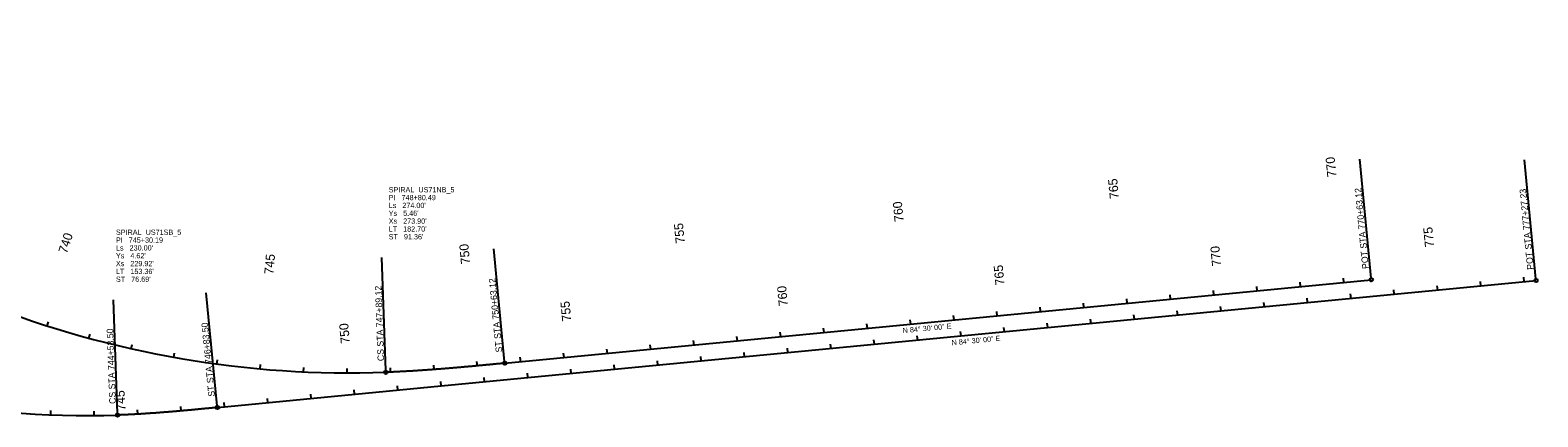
# Model space of a CAD drawing. Extents: x 2819977 to 2827606, y 113942 to 150283.
# Drawn here: x 2824142 to 2827606, y 145321 to 146209 of the extents above; entities that cross this region are included whole.
import ezdxf

# ---------------------------------------------------------------- set-up
doc = ezdxf.new("R2010")
doc.units = 0
for name, color, linetype in [('Level 63', 7, 'Continuous'), ('Roadway-Safety', 7, 'Continuous'), ('Roadway-Walls', 7, 'Continuous'), ('Utility-Power', 7, 'Continuous')]:
    doc.layers.add(name, color=color, linetype=linetype)

msp = doc.modelspace()

# ---------------------------------------------------------------- linework, layer by layer
at = {"layer": 'Level 63'}
for centre in [(2827223.3, 145635.6), (2827601.9, 145633.9), (2825232.5, 145443.9), (2824959.3, 145423.1), (2824572.2, 145342.1), (2824342.9, 145324.7)]:
    msp.add_circle(centre, 4, dxfattribs=at)
at = {"layer": 'Roadway-Safety'}
for p, q in [((2827222.9, 145639.6), (2827196.6, 145913)), ((2827601.6, 145637.8), (2827575.2, 145911.3)), ((2825232.1, 145447.9), (2825207.2, 145706.4)), ((2824959.2, 145427.1), (2824949.8, 145686.6)), ((2824342.8, 145328.7), (2824333.4, 145589.5)), ((2824571.8, 145346.1), (2824546.8, 145605.9))]:
    msp.add_line(p, q, dxfattribs=at)
at = {"layer": 'Utility-Power'}
for p, q in [((2825086.6, 145391.7), (2827601.9, 145633.9)), ((2825232.5, 145443.9), (2827223.3, 145635.6)), ((2826961.4, 145610.3), (2826960.4, 145620.3)), ((2827060.9, 145619.9), (2827060, 145629.9)), ((2827160.5, 145629.5), (2827159.5, 145639.5)), ((2827375.8, 145612.1), (2827374.8, 145622)), ((2827475.3, 145621.7), (2827474.3, 145631.6)), ((2827574.8, 145631.2), (2827573.9, 145641.2)), ((2826662.8, 145581.6), (2826661.8, 145591.5)), ((2826762.3, 145591.2), (2826761.3, 145601.1)), ((2826861.8, 145600.8), (2826860.9, 145610.7)), ((2826977.6, 145573.7), (2826976.6, 145583.7)), ((2827077.1, 145583.3), (2827076.2, 145593.3)), ((2827176.7, 145592.9), (2827175.7, 145602.9)), ((2827276.2, 145602.5), (2827275.3, 145612.4)), ((2826264.6, 145543.3), (2826263.6, 145553.2)), ((2826364.1, 145552.8), (2826363.2, 145562.8)), ((2826463.7, 145562.4), (2826462.7, 145572.4)), ((2826563.2, 145572), (2826562.3, 145582)), ((2826679, 145545), (2826678, 145554.9)), ((2826778.5, 145554.6), (2826777.6, 145564.5)), ((2826878.1, 145564.1), (2826877.1, 145574.1)), ((2824181.4, 145529.5), (2824184.4, 145539)), ((2825866.4, 145504.9), (2825865.5, 145514.9)), ((2825966, 145514.5), (2825965, 145524.5)), ((2826065.5, 145524.1), (2826064.6, 145534)), ((2826165.1, 145533.7), (2826164.1, 145543.6)), ((2826280.8, 145506.6), (2826279.9, 145516.6)), ((2826380.4, 145516.2), (2826379.4, 145526.2)), ((2826479.9, 145525.8), (2826478.9, 145535.8)), ((2826579.4, 145535.4), (2826578.5, 145545.4)), ((2824277.3, 145501.2), (2824279.9, 145510.9)), ((2824374.3, 145477.2), (2824376.5, 145487)), ((2825567.8, 145476.2), (2825566.9, 145486.1)), ((2825667.4, 145485.7), (2825666.4, 145495.7)), ((2825766.9, 145495.3), (2825765.9, 145505.3)), ((2825982.2, 145477.9), (2825981.2, 145487.8)), ((2826081.7, 145487.5), (2826080.8, 145497.4)), ((2826181.3, 145497.1), (2826180.3, 145507)), ((2824472.4, 145457.4), (2824474.1, 145467.3)), ((2824571.1, 145442), (2824572.5, 145451.9)), ((2825169.7, 145437.9), (2825168.7, 145447.9)), ((2825269.2, 145447.4), (2825268.2, 145457.4)), ((2825368.7, 145457), (2825367.8, 145466.9)), ((2825468.3, 145466.6), (2825467.3, 145476.5)), ((2825584, 145439.6), (2825583.1, 145449.5)), ((2825683.6, 145449.1), (2825682.6, 145459.1)), ((2825783.1, 145458.7), (2825782.2, 145468.7)), ((2825882.7, 145468.3), (2825881.7, 145478.3)), ((2824670.5, 145430.8), (2824671.4, 145440.8)), ((2824770.3, 145424), (2824770.7, 145434)), ((2824870.2, 145421.6), (2824870.3, 145431.6)), ((2824959.3, 145423.1), (2824959.3, 145423.1)), ((2824970.2, 145423.5), (2824969.8, 145433.5)), ((2825070, 145429.4), (2825069.3, 145439.4)), ((2825185.9, 145401.2), (2825184.9, 145411.2)), ((2825285.4, 145410.8), (2825284.5, 145420.8)), ((2825385, 145420.4), (2825384, 145430.3)), ((2825484.5, 145430), (2825483.5, 145439.9)), ((2824572.2, 145342.1), (2825086.6, 145391.7)), ((2824887.3, 145372.5), (2824886.3, 145382.4)), ((2824986.8, 145382), (2824985.8, 145392)), ((2825086.3, 145391.6), (2825085.4, 145401.6)), ((2824489.1, 145334.3), (2824488.2, 145344.3)), ((2824588.6, 145343.7), (2824587.7, 145353.7)), ((2824688.2, 145353.3), (2824687.2, 145363.2)), ((2824787.7, 145362.9), (2824786.8, 145372.8)), ((2824189.5, 145325.4), (2824189.9, 145335.3)), ((2824289.4, 145323.5), (2824289.4, 145333.5)), ((2824342.9, 145324.7), (2824342.9, 145324.7)), ((2824389.4, 145326.9), (2824388.8, 145336.9))]:
    msp.add_line(p, q, dxfattribs=at)
for centre, radius, start, end in [((2824274.6, 147233.3), 1909.9, 212.4335, 272.05), ((2824876.4, 147713.4), 2291.8, 224.9911, 272.075)]:
    msp.add_arc(centre, radius, start, end, dxfattribs=at)
for points in [[(2825232.5, 145443.9), (2825228.8, 145443.5), (2825225.1, 145443.2), (2825221.4, 145442.8), (2825217.8, 145442.5), (2825214.1, 145442.1), (2825210.4, 145441.8), (2825206.7, 145441.4), (2825203, 145441), (2825199.3, 145440.7), (2825195.6, 145440.3), (2825192, 145440), (2825188.3, 145439.6), (2825184.6, 145439.3), (2825180.9, 145438.9), (2825177.2, 145438.6), (2825173.5, 145438.3), (2825169.8, 145437.9), (2825166.2, 145437.6), (2825162.5, 145437.2), (2825158.8, 145436.9), (2825155.1, 145436.5), (2825151.4, 145436.2), (2825147.7, 145435.9), (2825144, 145435.5), (2825140.3, 145435.2), (2825136.7, 145434.9), (2825133, 145434.6), (2825129.3, 145434.2), (2825125.6, 145433.9), (2825121.9, 145433.6), (2825118.2, 145433.3), (2825114.5, 145433), (2825110.8, 145432.6), (2825107.1, 145432.3), (2825103.5, 145432), (2825099.8, 145431.7), (2825096.1, 145431.4), (2825092.4, 145431.1), (2825088.7, 145430.8), (2825085, 145430.5), (2825081.3, 145430.3), (2825077.6, 145430), (2825073.9, 145429.7), (2825070.2, 145429.4), (2825066.5, 145429.1), (2825062.8, 145428.9), (2825059.2, 145428.6), (2825055.5, 145428.3), (2825051.8, 145428.1), (2825048.1, 145427.8), (2825044.4, 145427.6), (2825040.7, 145427.3), (2825037, 145427.1), (2825033.3, 145426.8), (2825029.6, 145426.6), (2825025.9, 145426.4), (2825022.2, 145426.1), (2825018.5, 145425.9), (2825014.8, 145425.7), (2825011.1, 145425.5), (2825007.4, 145425.3), (2825003.7, 145425.1), (2825000, 145424.9), (2824996.3, 145424.7), (2824992.6, 145424.5), (2824988.9, 145424.3), (2824985.2, 145424.1), (2824981.5, 145424), (2824977.8, 145423.8), (2824974.1, 145423.6), (2824970.4, 145423.5), (2824966.7, 145423.3), (2824963, 145423.2), (2824959.3, 145423.1)], [(2824572.2, 145342.1), (2824569.1, 145341.8), (2824566, 145341.5), (2824562.9, 145341.2), (2824559.8, 145340.9), (2824556.7, 145340.6), (2824553.7, 145340.3), (2824550.6, 145340), (2824547.5, 145339.7), (2824544.4, 145339.5), (2824541.3, 145339.2), (2824538.2, 145338.9), (2824535.1, 145338.6), (2824532, 145338.3), (2824528.9, 145338), (2824525.8, 145337.7), (2824522.7, 145337.4), (2824519.6, 145337.1), (2824516.5, 145336.8), (2824513.4, 145336.5), (2824510.3, 145336.3), (2824507.2, 145336), (2824504.1, 145335.7), (2824501, 145335.4), (2824498, 145335.1), (2824494.9, 145334.9), (2824491.8, 145334.6), (2824488.7, 145334.3), (2824485.6, 145334), (2824482.5, 145333.8), (2824479.4, 145333.5), (2824476.3, 145333.2), (2824473.2, 145333), (2824470.1, 145332.7), (2824467, 145332.4), (2824463.9, 145332.2), (2824460.8, 145331.9), (2824457.7, 145331.7), (2824454.6, 145331.4), (2824451.5, 145331.2), (2824448.4, 145330.9), (2824445.3, 145330.7), (2824442.2, 145330.5), (2824439.1, 145330.2), (2824436, 145330), (2824432.9, 145329.8), (2824429.8, 145329.5), (2824426.7, 145329.3), (2824423.6, 145329.1), (2824420.5, 145328.9), (2824417.4, 145328.6), (2824414.3, 145328.4), (2824411.2, 145328.2), (2824408.1, 145328), (2824405, 145327.8), (2824401.9, 145327.6), (2824398.8, 145327.4), (2824395.7, 145327.2), (2824392.6, 145327.1), (2824389.5, 145326.9), (2824386.4, 145326.7), (2824383.3, 145326.5), (2824380.2, 145326.4), (2824377.1, 145326.2), (2824374, 145326), (2824370.9, 145325.9), (2824367.8, 145325.7), (2824364.7, 145325.6), (2824361.6, 145325.4), (2824358.4, 145325.3), (2824355.3, 145325.2), (2824352.2, 145325), (2824349.1, 145324.9), (2824346, 145324.8), (2824342.9, 145324.7)]]:
    msp.add_spline(points, degree=3, dxfattribs=at)

# ---------------------------------------------------------------- texts
at = {"layer": 'Roadway-Safety'}
for s, height, rotation, p in [('POT STA 770+63.12', 15, 95.5, (2827217.8, 145661.2)), ('POT STA 777+27.23', 15, 95.5, (2827596.5, 145659.4)), ('CS STA 747+89.12', 15, 92.075, (2824955.4, 145448.9)), ('ST STA 750+63.12', 15, 95.5, (2825227, 145469.5)), ('CS STA 744+53.50', 15, 92.05, (2824339, 145350.6)), ('ST STA 746+83.50', 15, 95.5, (2824566.7, 145367.7)), ('N 84%%d 30\' 00" E', 12, 5.5, (2826147.3, 145512.8)), ('N 84%%d 30\' 00" E', 12, 5.5, (2826259.8, 145484.8))]:
    msp.add_text(s, height=height, rotation=rotation, dxfattribs=at).set_placement(p)
at = {"layer": 'Roadway-Walls'}
for s, p in [('SPIRAL  US71NB_5', (2824965.9, 145836.4)), ('PI   748+80.49', (2824965.9, 145818.4)), ("Ys   5.46'", (2824965.9, 145782.4)), ("Ls   274.00'", (2824965.9, 145800.4)), ("Xs   273.90'", (2824965.9, 145764.4)), ("LT   182.70'", (2824965.9, 145746.4)), ('SPIRAL  US71SB_5', (2824339.2, 145738.8)), ('PI   745+30.19', (2824339.2, 145720.8)), ("ST   91.36'", (2824965.9, 145728.4)), ("Ys   4.62'", (2824339.2, 145684.8)), ("Ls   230.00'", (2824339.2, 145702.8)), ("Xs   229.92'", (2824339.2, 145666.8)), ("LT   153.36'", (2824339.2, 145648.8)), ("ST   76.69'", (2824339.2, 145630.8))]:
    msp.add_text(s, height=12, dxfattribs=at).set_placement(p)
at = {"layer": 'Utility-Power'}
for s, rotation, p in [(' 770', 95.5, (2827144.1, 145864.4)), (' 765', 95.5, (2826644.5, 145814.6)), (' 760', 95.5, (2826149.9, 145761.9)), (' 755', 95.5, (2825647.1, 145712.3)), (' 740', 72.3469, (2824224.1, 145687)), (' 775', 95.5, (2827368.5, 145703.3)), (' 745', 84.8469, (2824700, 145639.5)), (' 750', 95.3182, (2825153.8, 145664.5)), (' 770', 95.5, (2826879.4, 145659.7)), (' 765', 95.5, (2826381.7, 145616.1)), (' 760', 95.5, (2825884, 145568.1)), (' 755', 95.5, (2825386.3, 145533.1)), (' 750', 95.5, (2824877.8, 145482.2)), (' 745', 93.304, (2824362, 145327.6))]:
    msp.add_text(s, height=21, rotation=rotation, dxfattribs=at).set_placement(p)

doc.saveas('drawing.dxf')
